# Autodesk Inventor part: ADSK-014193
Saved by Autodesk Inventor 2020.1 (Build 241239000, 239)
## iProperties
Part Number: ADSK-014193
Material: Allgemein
Description: Framegenerator-Skeleton-Referenz
Document SubType Name: Modellieren
Designer: lutzd
Density: 1 g/cm^3
Appearance: Vorgabe
_SkeletonDoc: Frame Skeleton File
_Version: 15.0.0
DocNumber: ADSK-014177
Folder: .
Dimensions: 0x0x0 mm
Mass: 0 kg
Title: Gestellrahmenbauteil(e)
Author: lutzd
Revision Number: -
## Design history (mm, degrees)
sketch "Referenzrahmen"
node "Volumenkörper"
node "Flächenkörper"
